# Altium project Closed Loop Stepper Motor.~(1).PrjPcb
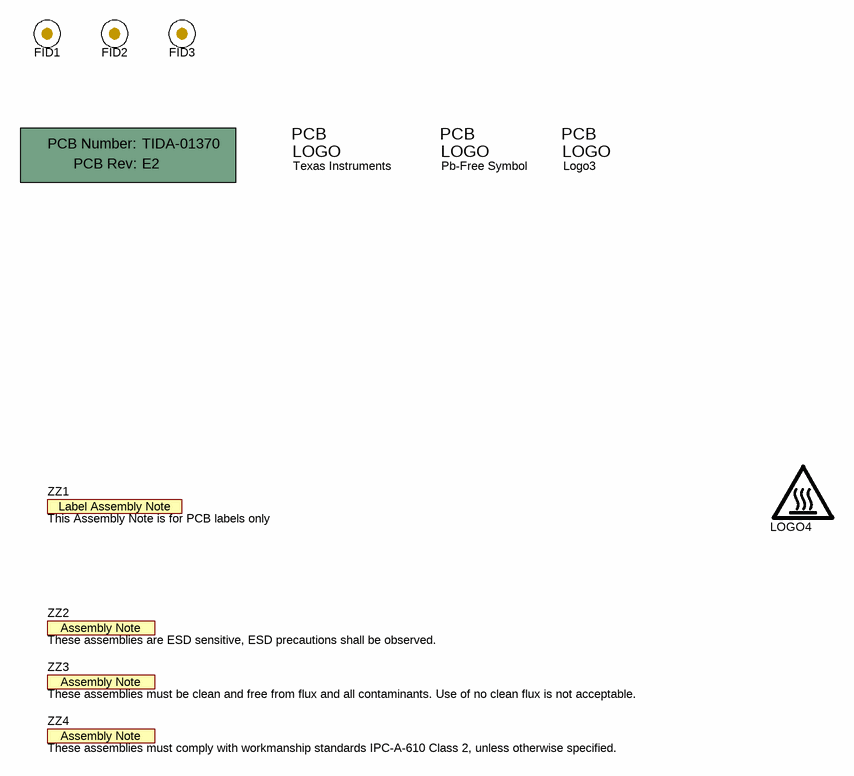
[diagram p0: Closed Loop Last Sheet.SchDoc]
TID: N/A; TechSupport: http://www.ti.com/support; SCH_Rev: E2; PRJ_Title: Change in menu Project|Project Options|Parameters; PRJ_Number: TIDA-01370; PRJ_Engineer: Rick Duncan; PRJ_Customer: Public Release; PCB_Rev: E2; PCB_Layout: Antonio Faggio; CopyrightYear: 2016
4 sheets, 67 parts. Net scope: global (net labels, ports and power ports of the same name join across sheets).
Board file: Closed Loop Stepper Motor Layout.PcbDoc
Sheets:
  Closed Loop Last Sheet.SchDoc
  Closed Loop PWR&Encoder.SchDoc
  Closed Loop DRV8880_MSP430.SchDoc
  Block Diagram_TIDA01370.SchDoc

## Sheet Closed Loop Last Sheet.SchDoc
size 431 x 279 mm; Date: Not shown in title block; ApprovedBy: Not shown in title block; CheckedBy: Not shown in title block; Author: Not shown in title block; CompanyName: Not shown in title block; Engineer: Not shown in title block; Organization: Not shown in title block; Address1: Not shown in title block; Address2: Not shown in title block; Address3: Not shown in title block; Address4: Not shown in title block; DocumentNumber: 4; Revision: Use project parameter SCH_Rev; SheetNumber: 4; SheetTotal: 4; PageSetup: Record=PageOptions¦CenterHorizontal=True¦CenterVertical=True¦PrintScale=1.00¦XCorrection=1.00¦YCorrection=1.00¦PrintKind=0¦BorderSize=5000000¦LeftOffset=0¦BottomOffset=0¦Orientation=2¦PaperLength=1000¦PaperWidth=1000¦Scale=100¦PaperSource=15¦PrintQuality=600¦MediaType=1¦DitherType=10¦PaperKind=Letter¦PrintScaleMode=1

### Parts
!PCB1  Printed Circuit Board  (value not drawn)  (mechanical)
FID1  Fiducial  [Fiducial10-20]  (value not drawn)
FID2  Fiducial  [Fiducial10-20]  (value not drawn)
FID3  Fiducial  [Fiducial10-20]  (value not drawn)
Logo1  Texas Instruments  [TI_Symbol_Overlay_Small]  (no BOM)
Logo2  Pb-Free Symbol  [Pb-Free_Overlay_Small]  (no BOM)
Logo3  FCC disclaimer  [FCC_disclaimer_stacked]  (value not drawn)  (no BOM)
LOGO4  CAUTION HOT SURFACE  [IEC_HotSurface_Small]  (value not drawn)  (no BOM)
ZZ1  This Assembly Note is for PCB labels only  [AssemblyNoteLabel]  (no BOM)
ZZ2  These assemblies are ESD sensitive, ESD precautions shall be observed.  [AssemblyNote]  (no BOM)
ZZ3  These assemblies must be clean and free from flux and all contaminants. Use of no clean flux is not acceptable.  [AssemblyNote]  (no BOM)
ZZ4  These assemblies must comply with workmanship standards IPC-A-610 Class 2, unless otherwise specified.  [AssemblyNote]  (no BOM)

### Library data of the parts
!PCB1 = PCB: Manufacturer: Any; PartNumber: TIDA-01370; SymbolCreator: a0412235
FID1-FID3 = Fiducial: Fiducial mark.  There is nothing to buy or mount.; SymbolCreator: codlsc
Logo1 = TI_Logo: Texas Instrument Corporate Signature; SymbolCreator: codlsc
Logo2 = Pb-Free: SymbolCreator: a0412235
Logo3 = FCC_disclaimer: SymbolCreator: a0412235
LOGO4 = IEC_HotSurface: IEC 61010-1 Hot Surface Warning; SymbolCreator: a0412235
ZZ1 = AssemblyNoteLabel: SymbolCreator: a0412235
ZZ2-ZZ4 = AssemblyNote: SymbolCreator: codlsc

## Sheet Closed Loop PWR&Encoder.SchDoc
size 431 x 279 mm; Date: Not shown in title block; ApprovedBy: Not shown in title block; CheckedBy: Not shown in title block; Author: Not shown in title block; CompanyName: Not shown in title block; Engineer: Not shown in title block; Organization: Not shown in title block; Address1: Not shown in title block; Address2: Not shown in title block; Address3: Not shown in title block; Address4: Not shown in title block; DocumentNumber: 3; Revision: Use project parameter SCH_Rev; SheetNumber: 3; SheetTotal: 4; PageSetup: Record=PageOptions¦CenterHorizontal=True¦CenterVertical=True¦PrintScale=1.00¦XCorrection=1.00¦YCorrection=1.00¦PrintKind=0¦BorderSize=5000000¦LeftOffset=0¦BottomOffset=0¦Orientation=2¦PaperLength=1000¦PaperWidth=1000¦Scale=100¦PaperSource=15¦PrintQuality=600¦MediaType=1¦DitherType=10¦PaperKind=Letter¦PrintScaleMode=1
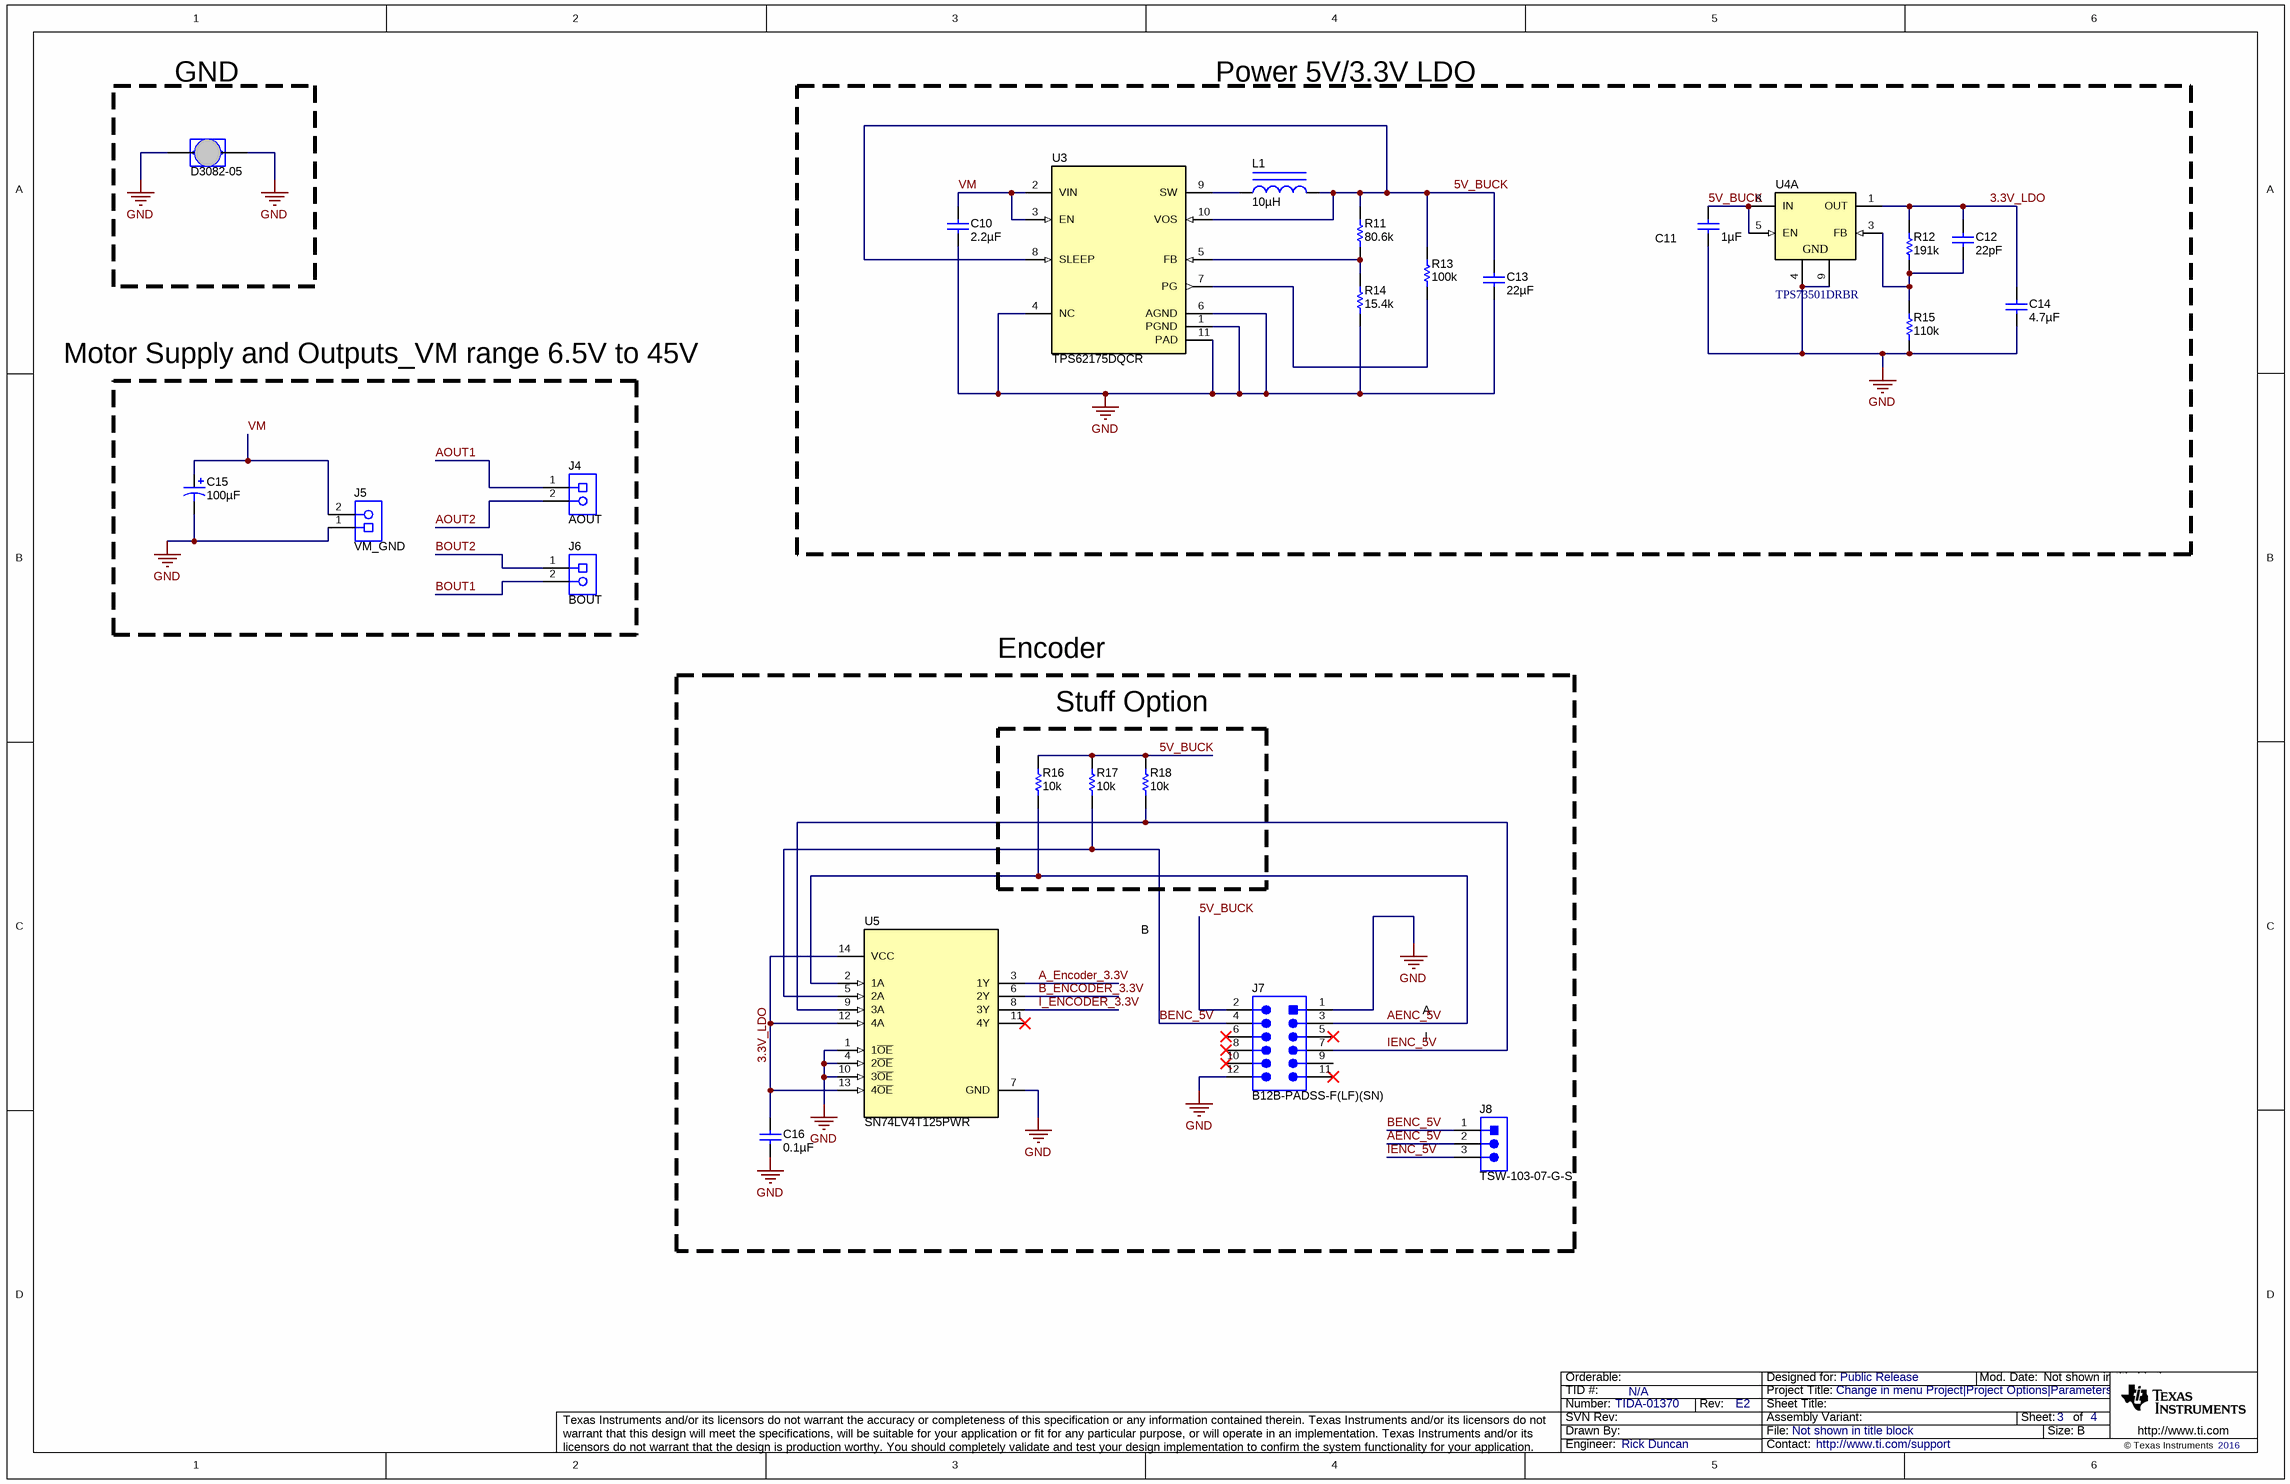
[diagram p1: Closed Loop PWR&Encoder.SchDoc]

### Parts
C10  ValueDisplayed: 2.2µF  [0805_HV]  (hidden comment: GRM21BR61E225KA12L)
C11  ValueDisplayed: 1µF  [0402L]  (hidden comment: C1005X5R0J105M050BB)
C12  ValueDisplayed: 22pF  [0402L]  (hidden comment: C1005C0G1H220J050BA)
C13  ValueDisplayed: 22µF  [1206_180]  (hidden comment: GRM31CR61A226ME19L)
C14  ValueDisplayed: 4.7µF  [0603L]  (hidden comment: GRM188R60J475KE19D)
C15  ValueDisplayed: 100µF  [SM_RADIAL_G]  (hidden comment: EEE-FK1J101P)
C16  ValueDisplayed: 0.1µF  [0603L]  (hidden comment: C0603C104K8RACTU)
J4  AOUT  [TERM_BLK_ED555-2DS]
J5  VM_GND  [TERM_BLK_ED555-2DS]
J6  BOUT  [TERM_BLK_ED555-2DS]
J7  B12B-PADSS-F(LF)(SN)  [JST_B12B-PADSS-F]
J8  TSW-103-07-G-S  [TSW-103-07-G-S]
L1  ValueDisplayed: 10µH  [WE-TPC_2828]  (hidden comment: 744025100)
R11  ValueDisplayed: 80.6k  [0402L]  (hidden comment: CRCW040280K6FKED)
R12  ValueDisplayed: 191k  [0402L]  (hidden comment: CRCW0402191KFKED)
R13  ValueDisplayed: 100k  [0402L]  (hidden comment: CRCW0402100KFKED)
R14  ValueDisplayed: 15.4k  [0402L]  (hidden comment: CRCW040215K4FKED)
R15  ValueDisplayed: 110k  [0402L]  (hidden comment: CRCW0402110KFKED)
R16  ValueDisplayed: 10k  [0603L]  (hidden comment: CRCW060310K0JNEA)
R17  ValueDisplayed: 10k  [0603L]  (hidden comment: CRCW060310K0JNEA)
R18  ValueDisplayed: 10k  [0603L]  (hidden comment: CRCW060310K0JNEA)
TP1  D3082-05  [Harwin_D3082-05]
U3  TPS62175DQCR  [DQC0010A]
U4  TPS73501DRBR  [DRB0008A]  (part A of 2)
U5  SN74LV4T125PWR  [PW0014A_N]

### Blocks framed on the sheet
GND: TP1
Power 5V/3.3V LDO: C10-C14 L1 R11-R15 U3 U4
Stuff Option: C16 J7 J8 R16-R18 U5

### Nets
3.3V_LDO: C12.1 C14.1 C16.1 R12.2 U4.1(OUT) U5.12(4A) U5.13(4~{OE}) U5.14(VCC)
GND: C10.2 C11.1 C13.2 C14.2 C15.2(-) C16.2 J5.1 J7.1 J7.12 R14.2 R15.1 TP1.1 TP1.2 U3.1(PGND) U3.4(NC) U3.6(AGND) U3.11(PAD) U4.4(GND) U4.9(GND) U5.1(1~{OE}) U5.4(2~{OE}) U5.7(GND) U5.10(3~{OE})
5V_BUCK: C11.2 C13.1 J7.2 L1.2 R11.2 R13.2 R16.2 R17.2 R18.2 U3.8(SLEEP) U3.10(VOS) U4.5(EN) U4.8(IN)
A_Encoder_3.3V: U5.3(1Y)
AENC_5V: J7.3 J8.2 R16.1 U5.2(1A)
AOUT1: J4.1
AOUT2: J4.2
B_ENCODER_3.3V: U5.6(2Y)
BENC_5V: J7.4 J8.1 R17.1 U5.5(2A)
BOUT1: J6.2
BOUT2: J6.1
I_ENCODER_3.3V: U5.8(3Y)
IENC_5V: J7.7 J8.3 R18.1 U5.9(3A)
VM: C10.1 C15.1(+) J5.2 U3.2(VIN) U3.3(EN)
NetC12_2: C12.2 R12.1 R15.2 U4.3(FB)
NetL1_1: L1.1 U3.9(SW)
NetR11_1: R11.1 R14.1 U3.5(FB)
NetR13_1: R13.1 U3.7(PG)

Not connected (* = marked no-connect by the designer): J7 5* 6* 8* 9 10* 11*; U5 11(4Y)*

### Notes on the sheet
- Motor Supply and Outputs_VM range 6.5V to 45V
- Encoder
- B
- A
- I

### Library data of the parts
C10 = GRM21BR61E225KA12L: CAP, CERM, 2.2 µF, 25 V, +/- 10%, X5R, 0805; Manufacturer: MuRata; Polarized: N; CompType: Capacitor; Value: 2.2uF; U/M: EA; Cap_F: 0.0000022; Tolerance_%: 10; ESR_ohm: 0.008; Value1: 0.008 ohm; VDC_V: 25; Value2: 25V; TaMin_C: -55; TaMax_C: 85; Cap_Case: 0805; SizeArea_mm2: 2.5; SizeAreaWB_mm2: 6.75; SizeX_mm: 2; SizeY_mm: 1.25; SizeZ_mm: 1.45; AEC Category: Q200
C11 = C1005X5R0J105M050BB: CAP, CERM, 1 µF, 6.3 V, +/- 20%, X5R, 0402; Manufacturer: TDK; Polarized: N; CompType: Capacitor; Value: 1uF; U/M: EA; Cap_F: 0.000001; Tolerance_%: 20; ESR_ohm: 0.0079; Value1: 0.0079 ohm; VDC_V: 6.3; Value2: 6.3V; TaMin_C: -55; TaMax_C: 85; Cap_Case: 0402; SizeArea_mm2: 0.5; SizeAreaWB_mm2: 3; SizeX_mm: 1; SizeZ_mm: 0.6; AEC Category: Q200
C12 = C1005C0G1H220J050BA: CAP, CERM, 22 pF, 50 V, +/- 5%, C0G/NP0, 0402; Manufacturer: TDK; Polarized: N; CompType: Capacitor; Value: 22pF; U/M: EA; Cap_F: 0.000000000022; Tolerance_%: 5; Value1: Unknown; VDC_V: 50; Value2: 50V; TaMin_C: -55; TaMax_C: 125; Cap_Case: 0402; SizeArea_mm2: 0.5; SizeAreaWB_mm2: 3; SizeX_mm: 1; SizeZ_mm: 0.6; AEC Category: Q200
C13 = GRM31CR61A226ME19L: CAP, CERM, 22 µF, 10 V, +/- 20%, X5R, 1206; Manufacturer: MuRata; Polarized: N; CompType: Capacitor; Value: 22uF; U/M: EA; Cap_F: 0.000022; Tolerance_%: 20; ESR_ohm: 0.007; Value1: 0.007 ohm; VDC_V: 10; Value2: 10V; TaMin_C: -55; TaMax_C: 85; Cap_Case: 1206; SizeArea_mm2: 5.12; SizeAreaWB_mm2: 10.92; SizeX_mm: 3.2; SizeY_mm: 1.6; SizeZ_mm: 1.8; AEC Category: Q200
C14 = GRM188R60J475KE19D: CAP, CERM, 4.7 µF, 6.3 V, +/- 10%, X5R, 0603; Manufacturer: MuRata; Polarized: N; CompType: Capacitor; Value: 4.7uF; U/M: EA; Cap_F: 0.0000047; Tolerance_%: 10; ESR_ohm: 0.005; Value1: 0.005 ohm; VDC_V: 6.3; Value2: 6.3V; IRMS_A: 2; TaMin_C: -55; TaMax_C: 85; Cap_Case: 0603; SizeArea_mm2: 1.28; SizeAreaWB_mm2: 4.68; SizeX_mm: 1.6; SizeY_mm: 0.8; SizeZ_mm: 1; AEC Category: Q200
C15 = EEE-FK1J101P: CAP, AL, 100 µF, 63 V, +/- 20%, 0.35 ohm, AEC-Q200 Grade 2, SMD; Manufacturer: Panasonic; Polarized: Y; CompType: Capacitor; Value: 100uF; U/M: EA; Cap_F: 0.0001; Tolerance_%: 20; VDC_V: 63; Value2: 63V; ESR_ohm: 0.35; IRMS_A: 0.4; TaMin_C: -55; TaMax_C: 105; Cap_Case: G; SizeAreaWB_mm2: 172.2; SizeArea_mm2: 123.6; SizeX_mm: 12; SizeY_mm: 10.3; SizeZ_mm: 10.2; AEC Category: Q200; AEC Grade: 2
C16 = C0603C104K8RACTU: CAP, CERM, 0.1 µF, 10 V, +/- 10%, X7R, 0603; Manufacturer: Kemet; Polarized: N; CompType: Capacitor; Value: 0.1uF; U/M: EA; Cap_F: 0.0000001; Tolerance_%: 10; Value1: Unknown; Value2: 10V; TaMin_C: -55; TaMax_C: 125; Cap_Case: 0603; SizeArea_mm2: 1.28; SizeAreaWB_mm2: 4.68; SizeX_mm: 1.6; SizeY_mm: 0.8; SizeZ_mm: 1; AEC Category: Q200
J4-J6 = ED555/2DS: Terminal Block, 3.5mm Pitch, 2x1, TH; Manufacturer: On-Shore Technology; SymbolCreator: a0412235; Pitch_mm: 3.5; Gender: Female; Shrouded: N; Row_Count: 1; ContactFinish: Brass; Current_A: 6; Voltage_V: 150; Cert_CULUS: Y
J7 = B12B-PADSS-F(LF)(SN): Header(Shrouded), 2mm, 6x2, Tin, TH; Manufacturer: JST Manufacturing; SymbolCreator: Altium; Pitch_mm: 2; Gender: Male; Shrouded: Y; Current_A: 3; Voltage_V: 250
J8 = TSW-103-07-G-S: Header, 100mil, 3x1, Gold, TH; Manufacturer: Samtec; SymbolCreator: a0799628; Pitch_mm: 2.54; Gender: Male; Shrouded: N; Row_Count: 1; Current_A: 6.3; Voltage_V: 550; Cert_CSA: Y
L1 = 744025100: Inductor, Shielded Drum Core, Ferrite, 10 µH, 1 A, 0.17 ohm, SMD; Manufacturer: Wurth Elektronik; Value: 10uH; Ind_H: 10.0E-6; Imax_A: 1; Irms: 1A @ 40C rise; Isat: 1.1A @ 35% inductance drop; DCR_ohm: 0.17; Value2: 1A; SizeAreaWB_mm2: 14.44; SizeArea_mm2: 7.84; SizeX_mm: 2.8; SizeZ_mm: 3; AEC Category: Q200
R11 = CRCW040280K6FKED: RES, 80.6 k, 1%, 0.063 W, 0402; Manufacturer: Vishay-Dale; CompType: Resistor; Value: 80.6k; Res_ohm: 80600; Value_Code: 80k6; Tolerance_%: 1; Power_W: 0.063; Value2: 0.063W; VDC_V: 50; TempCo: 100 ppm/C; SizeArea_mm2: 0.5; SizeZ_mm: 0.6; EIA_Code: E96; U/M: EA; AEC Category: Q200
R12 = CRCW0402191KFKED: RES, 191 k, 1%, 0.063 W, 0402; Manufacturer: Vishay-Dale; CompType: Resistor; Value: 191k; Res_ohm: 191000; Tolerance_%: 1; Power_W: 0.063; Value2: 0.063W; VDC_V: 50; TempCo: 100 ppm/C; SizeArea_mm2: 0.5; SizeZ_mm: 0.6; EIA_Code: E96; U/M: EA; AEC Category: Q200
R13 = CRCW0402100KFKED: RES, 100 k, 1%, 0.063 W, 0402; Manufacturer: Vishay-Dale; CompType: Resistor; Value: 100k; Res_ohm: 100000; Tolerance_%: 1; Power_W: 0.063; Value2: 0.063W; VDC_V: 50; TempCo: 100 ppm/C; SizeArea_mm2: 0.5; SizeZ_mm: 0.6; EIA_Code: E96; U/M: EA; AEC Category: Q200
R14 = CRCW040215K4FKED: RES, 15.4 k, 1%, 0.063 W, 0402; Manufacturer: Vishay-Dale; CompType: Resistor; Value: 15.4k; Res_ohm: 15400; Value_Code: 15k4; Tolerance_%: 1; Power_W: 0.063; Value2: 0.063W; VDC_V: 50; TempCo: 100 ppm/C; SizeArea_mm2: 0.5; SizeZ_mm: 0.6; EIA_Code: E96; U/M: EA; AEC Category: Q200
R15 = CRCW0402110KFKED: RES, 110 k, 1%, 0.063 W, 0402; Manufacturer: Vishay-Dale; CompType: Resistor; Value: 110k; Res_ohm: 110000; Tolerance_%: 1; Power_W: 0.063; Value2: 0.063W; VDC_V: 50; TempCo: 100 ppm/C; SizeArea_mm2: 0.5; SizeZ_mm: 0.6; EIA_Code: E96; U/M: EA; AEC Category: Q200
R16-R18 = CRCW060310K0JNEA: RES, 10 k, 5%, 0.1 W, 0603; Manufacturer: Vishay-Dale; CompType: Resistor; Value: 10k; Res_ohm: 10000; Value_Code: 10k0; Tolerance_%: 5; Power_W: 0.1; Value2: 0.1W; VDC_V: 75; TempCo: 200 ppm/C; SizeArea_mm2: 1.28; SizeX_mm: 1.6; SizeY_mm: 0.8; SizeZ_mm: 1; EIA_Code: E24; U/M: EA; AEC Category: Q200
TP1 = D3082-05: 1mm Uninsulated Shorting Plug, 10.16mm spacing, TH; Manufacturer: Harwin; SymbolCreator: a0799628; CompType: Jumper Wire
U3 = TPS62175DQCR: 28V, 0.5A Step-Down Converter with Sleep Mode, DQC0010A (WSON-10); Alternate PartNumber: TPS62175DQCT; Manufacturer: Texas Instruments; SymbolCreator: a0411947; SizeArea_mm2: 6; SizeAreaWB_mm2: 12; SizeX_mm: 2; SizeY_mm: 3; SizeZ_mm: 0.8; CompType: IC; U/M: EA
U4 = TPS73501DRBR: Single Output High PSRR LDO, 500 mA, Adjustable 1.25 to 6 V Output, 2.7 to 6.5 V Input, with Low IQ, 8-pin SON (DRB), -40 to 125 degC, Green (RoHS & no Sb/Br); Manufacturer: Texas Instruments; Alternate PartNumber: Equivalent; Accuracy(%): 2; Iout(Max)(A): 0.5; Iq(Typ)(mA): 0.04; SubFamily: Single Channel LDO; Vdo(Typ)(mV): 280; Vin(Max)(V): 6.5; Vin(Min)(V): 2.7; Vout Adj(Max)(V): 6; Vout Adj(Min)(V): 1.25
U5 = SN74LV4T125PWR: Single Power Supply Quadruple Buffer Translator GATE With 3-State Output CMOS Logic Level Shifter, PW0014A (TSSOP-14); Manufacturer: Texas Instruments; SymbolCreator: Altium; SizeArea_mm2: 32; SizeAreaWB_mm2: 58.8; SizeX_mm: 6.4; SizeY_mm: 5; SizeZ_mm: 1.2; CompType: IC; U/M: EA

## Sheet Closed Loop DRV8880_MSP430.SchDoc
size 431 x 279 mm; Date: Not shown in title block; ApprovedBy: Not shown in title block; CheckedBy: Not shown in title block; Author: Not shown in title block; CompanyName: Not shown in title block; Engineer: Not shown in title block; Organization: Not shown in title block; Address1: Not shown in title block; Address2: Not shown in title block; Address3: Not shown in title block; Address4: Not shown in title block; DocumentNumber: 2; Revision: Use project parameter SCH_Rev; SheetNumber: 2; SheetTotal: 4; PageSetup: Record=PageOptions¦CenterHorizontal=True¦CenterVertical=True¦PrintScale=0.62¦XCorrection=1.00¦YCorrection=1.00¦PrintKind=0¦BorderSize=5000000¦LeftOffset=0¦BottomOffset=0¦Orientation=2¦PaperLength=1000¦PaperWidth=1000¦Scale=100¦PaperSource=15¦PrintQuality=600¦MediaType=1¦DitherType=10¦PrintScaleMode=1¦PaperKind=Letter
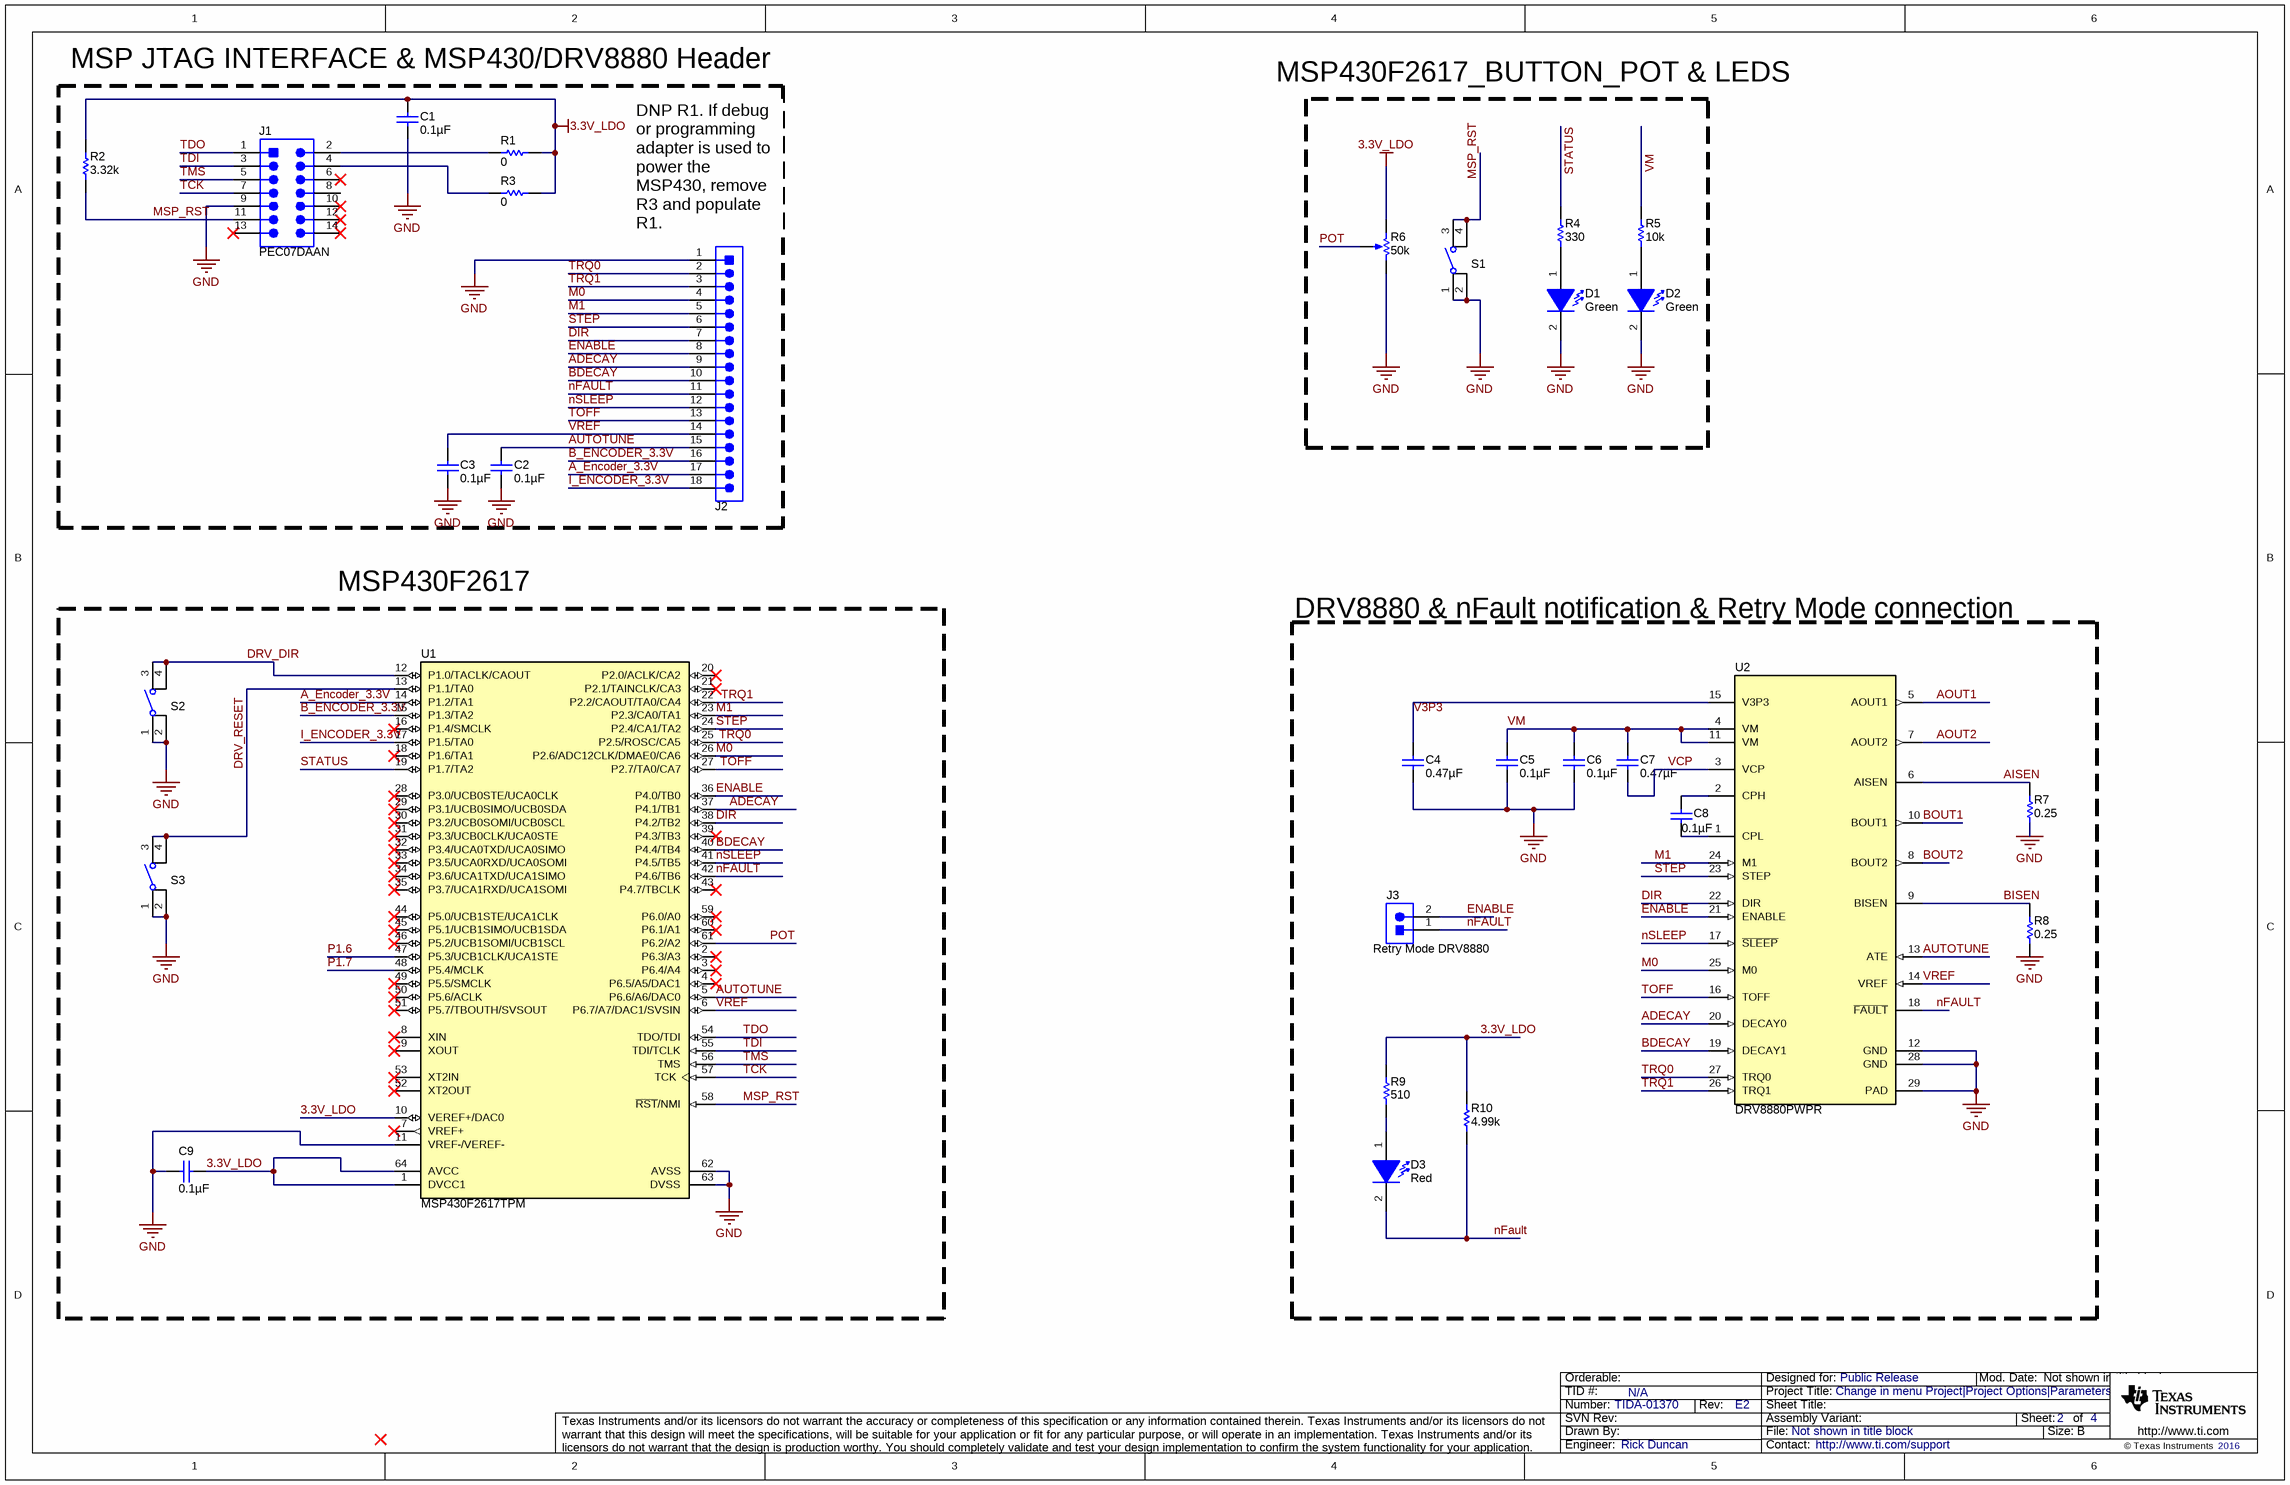
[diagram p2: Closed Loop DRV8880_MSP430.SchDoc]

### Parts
C1  ValueDisplayed: 0.1µF  [0402L]  (hidden comment: GRM155R61A104KA01D)
C2  ValueDisplayed: 0.1µF  [0402L]  (hidden comment: GRM155R61A104KA01D)
C3  ValueDisplayed: 0.1µF  [0402L]  (hidden comment: GRM155R61A104KA01D)
C4  ValueDisplayed: 0.47µF  [0603L]  (hidden comment: C0603C474K9RACTU)
C5  ValueDisplayed: 0.1µF  [0805L]  (hidden comment: C0805C104K1RACTU)
C6  ValueDisplayed: 0.1µF  [0805L]  (hidden comment: C0805C104K1RACTU)
C7  ValueDisplayed: 0.47µF  [0805L]  (hidden comment: 0805YC474KAT2A)
C8  ValueDisplayed: 0.1µF  [0805L]  (hidden comment: GRM21BR71E104KA01L)
C9  ValueDisplayed: 0.1µF  [0402L]  (hidden comment: GRM155R61A104KA01D)
D1  value Green  [LED_LTST-C171]  (hidden comment: LTST-C171GKT)
D2  value Green  [LED_LTST-C171]  (hidden comment: LTST-C171GKT)
D3  value Red  [LED_LTST-C190_Red]  (hidden comment: LTST-C190CKT)
J1  PEC07DAAN  [CONN_PEC07DAAN]
J2  TSW-118-07-G-S  [TSW-118-07-G-S]  (value not drawn)
J3  Retry Mode DRV8880  [CONN_90120-0122]
R1  ValueDisplayed: 0  [0402L]  (hidden comment: ERJ-2GE0R00X)
R2  ValueDisplayed: 3.32k  [0402L]  (hidden comment: CRCW04023K32FKED)
R3  ValueDisplayed: 0  [0402L]  (hidden comment: ERJ-2GE0R00X)
R4  ValueDisplayed: 330  [0603L]  (hidden comment: CRCW0603330RJNEA)
R5  ValueDisplayed: 10k  [0603L]  (hidden comment: CRCW060310K0JNEA)
R6  value 50k  [Bourns_3352T]  (hidden comment: 3352T-1-503LF)
R7  ValueDisplayed: 0.25  [2010L]  (hidden comment: CSRN2010FKR250)
R8  ValueDisplayed: 0.25  [2010L]  (hidden comment: CSRN2010FKR250)
R9  ValueDisplayed: 510  [0402L]  (hidden comment: CRCW0402510RJNED)
R10  ValueDisplayed: 4.99k  [0402L]  (hidden comment: CRCW04024K99FKED)
S1  4-1437565-1  [SW_FSM4JSMA]  (value not drawn)
S2  4-1437565-1  [SW_FSM4JSMA]  (value not drawn)
S3  4-1437565-1  [SW_FSM4JSMA]  (value not drawn)
U1  MSP430F2617TPM  [PM0064A_N]
U2  DRV8880PWPR  [PWP0028C_N]

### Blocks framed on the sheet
DRV8880 & nFault notification & Retry Mode connection: C4-C8 D3 J3 R7-R10 U2

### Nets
3.3V_LDO: C1.1 C9.2 R1.2 R2.2 R3.2 R6.3(CW) R9.2 R10.2 U1.1(DVCC1) U1.10(VEREF+/DAC0) U1.64(AVCC)
GND: C1.2 C2.2 C3.2 C4.2 C5.2 C6.2 C9.1 D1.2(K) D2.2(K) J1.9 J2.1 R6.1(CCW) R7.1 R8.1 S1.1 S1.2 S2.1 S2.2 S3.1 S3.2 U1.11(VREF-/VEREF-) U1.62(AVSS) U1.63(DVSS) U2.12(GND) U2.28(GND) U2.29(PAD)
A_Encoder_3.3V: J2.17 U1.14(P1.2/TA1)
ADECAY: J2.9 U1.37(P4.1/TB1) U2.20(DECAY0)
AISEN: R7.2 U2.6(AISEN)
AOUT1: U2.5(AOUT1)
AOUT2: U2.7(AOUT2)
AUTOTUNE: C2.1 J2.15 U1.5(P6.6/A6/DAC0) U2.13(ATE)
B_ENCODER_3.3V: J2.16 U1.15(P1.3/TA2)
BDECAY: J2.10 U1.40(P4.4/TB4) U2.19(DECAY1)
BISEN: R8.2 U2.9(BISEN)
BOUT1: U2.10(BOUT1)
BOUT2: U2.8(BOUT2)
DIR: J2.7 U1.38(P4.2/TB2) U2.22(DIR)
DRV_DIR: S2.3 S2.4 U1.12(P1.0/TACLK/CAOUT)
DRV_RESET: S3.3 S3.4 U1.13(P1.1/TA0)
ENABLE: J2.8 J3.2 U1.36(P4.0/TB0) U2.21(ENABLE)
I_ENCODER_3.3V: J2.18 U1.17(P1.5/TA0)
M0: J2.4 U1.26(P2.6/ADC12CLK/DMAE0/CA6) U2.25(M0)
M1: J2.5 U1.23(P2.3/CA0/TA1) U2.24(M1)
MSP_RST: J1.11 R2.1 S1.3 S1.4 U1.58(~{RST}/NMI)
nFAULT: D3.2(K) J2.11 J3.1 R10.1 U1.42(P4.6/TB6) U2.18(~{FAULT})
nSLEEP: J2.12 U1.41(P4.5/TB5) U2.17(~{SLEEP})
P1.6: U1.47(P5.3/UCB1CLK/UCA1STE)
P1.7: U1.48(P5.4/MCLK)
POT: R6.2(WIPER) U1.61(P6.2/A2)
STATUS: R4.2 U1.19(P1.7/TA2)
STEP: J2.6 U1.24(P2.4/CA1/TA2) U2.23(STEP)
TCK: J1.7 U1.57(TCK)
TDI: J1.3 U1.55(TDI/TCLK)
TDO: J1.1 U1.54(TDO/TDI)
TMS: J1.5 U1.56(TMS)
TOFF: J2.13 U1.27(P2.7/TA0/CA7) U2.16(TOFF)
TRQ0: J2.2 U1.25(P2.5/ROSC/CA5) U2.27(TRQ0)
TRQ1: J2.3 U1.22(P2.2/CAOUT/TA0/CA4) U2.26(TRQ1)
V3P3: C4.1 U2.15(V3P3)
VCP: C7.1 U2.3(VCP)
VM: C5.1 C6.1 C7.2 R5.2 U2.4(VM) U2.11(VM)
VREF: C3.1 J2.14 U1.6(P6.7/A7/DAC1/SVSIN) U2.14(VREF)
NetC8_1: C8.1 U2.2(CPH)
NetC8_2: C8.2 U2.1(CPL)
NetD1_1: D1.1(A) R4.1
NetD2_1: D2.1(A) R5.1
NetD3_1: D3.1(A) R9.1
NetJ1_2: J1.2 R1.1
NetJ1_4: J1.4 R3.1

Not connected (* = marked no-connect by the designer): J1 6* 8 10* 12* 13* 14*; U1 2(P6.3/A3)* 3(P6.4/A4)* 4(P6.5/A5/DAC1)* 7(VREF+)* 8(XIN)* 9(XOUT)* 16(P1.4/SMCLK)* 18(P1.6/TA1)* 20(P2.0/ACLK/CA2)* 21(P2.1/TAINCLK/CA3)* 28(P3.0/UCB0STE/UCA0CLK)* 29(P3.1/UCB0SIMO/UCB0SDA)* 30(P3.2/UCB0SOMI/UCB0SCL)* 31(P3.3/UCB0CLK/UCA0STE)* 32(P3.4/UCA0TXD/UCA0SIMO)* 33(P3.5/UCA0RXD/UCA0SOMI)* 34(P3.6/UCA1TXD/UCA1SIMO)* 35(P3.7/UCA1RXD/UCA1SOMI)* 39(P4.3/TB3)* 43(P4.7/TBCLK)* 44(P5.0/UCB1STE/UCA1CLK)* 45(P5.1/UCB1SIMO/UCB1SDA)* 46(P5.2/UCB1SOMI/UCB1SCL)* 49(P5.5/SMCLK)* 50(P5.6/ACLK)* 51(P5.7/TBOUTH/SVSOUT)* 52(XT2OUT)* 53(XT2IN)* 59(P6.0/A0)* 60(P6.1/A1)*

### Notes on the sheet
- (near C1) MSP JTAG INTERFACE & MSP430/DRV8880 Header
- MSP430F2617_BUTTON_POT & LEDS
- (near J2) DNP R1. If debug or programming adapter is used to power the MSP430, remove R3 and populate R1.
- MSP430F2617

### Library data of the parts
C1-C3 C9 = GRM155R61A104KA01D: CAP, CERM, 0.1 µF, 10 V, +/- 10%, X5R, 0402; Manufacturer: MuRata; Polarized: N; CompType: Capacitor; Value: 0.1uF; U/M: EA; Cap_F: 0.0000001; Tolerance_%: 10; Value1: Unknown; Value2: 10V; TaMin_C: -55; TaMax_C: 85; Cap_Case: 0402; SizeArea_mm2: 0.5; SizeAreaWB_mm2: 3; SizeX_mm: 1; SizeZ_mm: 0.6; AEC Category: Q200
C4 = C0603C474K9RACTU: CAP, CERM, 0.47 µF, 6.3 V, +/- 10%, X7R, 0603; Manufacturer: Kemet; Polarized: N; CompType: Capacitor; Value: 0.47uF; U/M: EA; Cap_F: 0.00000047; Tolerance_%: 10; Value1: Unknown; VDC_V: 6.3; Value2: 6.3V; TaMin_C: -55; TaMax_C: 125; Cap_Case: 0603; SizeArea_mm2: 1.28; SizeAreaWB_mm2: 4.68; SizeX_mm: 1.6; SizeY_mm: 0.8; SizeZ_mm: 1; AEC Category: Q200
C5 C6 = C0805C104K1RACTU: CAP, CERM, 0.1 µF, 100 V, +/- 10%, X7R, 0805; Manufacturer: Kemet; Polarized: N; CompType: Capacitor; Value: 0.1uF; U/M: EA; Cap_F: 0.0000001; Tolerance_%: 10; ESR_ohm: 0.064; Value1: 0.064 ohm; VDC_V: 100; Value2: 100V; IRMS_A: 1.64; TaMin_C: -55; TaMax_C: 125; Cap_Case: 0805; SizeArea_mm2: 2.5; SizeAreaWB_mm2: 6.75; SizeX_mm: 2; SizeY_mm: 1.25; SizeZ_mm: 1.45; AEC Category: Q200
C7 = 0805YC474KAT2A: CAP, CERM, 0.47 µF, 16 V, +/- 10%, X7R, 0805; Manufacturer: AVX; Polarized: N; CompType: Capacitor; Value: 0.47uF; U/M: EA; Cap_F: 0.00000047; Tolerance_%: 10; ESR_ohm: 0.011; Value1: 0.011 ohm; VDC_V: 16; Value2: 16V; TaMin_C: -55; TaMax_C: 125; Cap_Case: 0805; SizeArea_mm2: 2.5; SizeAreaWB_mm2: 6.75; SizeX_mm: 2; SizeY_mm: 1.25; SizeZ_mm: 1.45; AEC Category: Q200
C8 = GRM21BR71E104KA01L: CAP, CERM, 0.1 µF, 25 V, +/- 10%, X7R, 0805; Manufacturer: MuRata; Polarized: N; CompType: Capacitor; Value: 0.1uF; U/M: EA; Cap_F: 0.0000001; Tolerance_%: 10; Value1: Unknown; VDC_V: 25; Value2: 25V; TaMin_C: -55; TaMax_C: 125; Cap_Case: 0805; SizeArea_mm2: 2.5; SizeAreaWB_mm2: 6.75; SizeX_mm: 2; SizeY_mm: 1.25; SizeZ_mm: 1.45; AEC Category: Q200
D1 D2 = LTST-C171GKT: LED, Green, SMD; Manufacturer: Lite-On; Type: AlInGaP; Vf_V: 2.1; Value2: 2.1V; Io_A: 20; Value1: W; SizeAreaWB_mm2: 6.75; SizeArea_mm2: 2.5; SizeX_mm: 2; SizeY_mm: 1.25; SizeZ_mm: 1.2; U/M: EA
D3 = LTST-C190CKT: LED, Red, SMD; Manufacturer: Lite-On; Vf_V: 2; Value2: 2V; Io_A: 0.02; Tjmax_C: 85; Power_TotalModule: 0.0625; Value1: 0.0625W; U/M: EA
J1 = PEC07DAAN: Header, 100mil, 7x2, Tin, TH; Manufacturer: Sullins Connector Solutions; SymbolCreator: a0412235; Pitch_mm: 2.54; Gender: Male; Shrouded: N; Row_Count: 2; Current_A: 3; Voltage_V: 1800; Cert_UL: Y
J2 = TSW-118-07-G-S: Header, 100mil, 18x1, Gold, TH; Manufacturer: Samtec; SymbolCreator: a0411947; Pitch_mm: 2.54; Gender: Male; Shrouded: N; Row_Count: 1; Current_A: 6.3; Voltage_V: 550; Cert_CSA: Y
J3 = 90120-0122: Header, 100mil, 2x1, Tin, TH; Manufacturer: Molex; SymbolCreator: a0412235
R1 R3 = ERJ-2GE0R00X: RES, 0, 5%, 0.063 W, 0402; Manufacturer: Panasonic; CompType: Resistor; Value: 0; Value_Code: 0000; Tolerance_%: 5; Power_W: 0.063; Value2: 0.063W; VDC_V: 50; TempCo: 600 ppm/C; SizeArea_mm2: 0.5; SizeX_mm: 1; SizeZ_mm: 0.6; EIA_Code: E24; U/M: EA; AEC Category: Q200
R2 = CRCW04023K32FKED: RES, 3.32 k, 1%, 0.063 W, 0402; Manufacturer: Vishay-Dale; CompType: Resistor; Value: 3.32k; Res_ohm: 3320; Value_Code: 3k32; Tolerance_%: 1; Power_W: 0.063; Value2: 0.063W; VDC_V: 50; TempCo: 100 ppm/C; SizeArea_mm2: 0.5; SizeZ_mm: 0.6; EIA_Code: E96; U/M: EA; AEC Category: Q200
R4 = CRCW0603330RJNEA: RES, 330, 5%, 0.1 W, 0603; Manufacturer: Vishay-Dale; CompType: Resistor; Value: 330; Value_Code: 330R; Tolerance_%: 5; Power_W: 0.1; Value2: 0.1W; VDC_V: 75; TempCo: 200 ppm/C; SizeArea_mm2: 1.28; SizeX_mm: 1.6; SizeY_mm: 0.8; SizeZ_mm: 1; EIA_Code: E24; U/M: EA; AEC Category: Q200
R5 = CRCW060310K0JNEA: as R16 on sheet Closed Loop PWR&Encoder
R6 = 3352T-1-503LF: Trimming Potentiometer, 50K, 0.5W, TH; Manufacturer: Bourns; Sim Note: Enter the Resistance value and the set point into parameter fields.; SymbolCreator: a0412235; CompType: Trimmer
R7 R8 = CSRN2010FKR250: RES, 0.25, 1%, 1 W, 2010; Manufacturer: Stackpole Electronics Inc; CompType: Resistor; Value: 0.25; Value_Code: R250; Tolerance_%: 1; Value2: 1W; TempCo: 250 ppm/C; SizeArea_mm2: 12.5; SizeX_mm: 5; SizeY_mm: 2.5; SizeZ_mm: 1.66; U/M: EA; AEC Category: Q200
R9 = CRCW0402510RJNED: RES, 510, 5%, 0.063 W, 0402; Manufacturer: Vishay-Dale; CompType: Resistor; Value: 510; Value_Code: 510R; Tolerance_%: 5; Power_W: 0.063; Value2: 0.063W; VDC_V: 50; TempCo: 200 ppm/C; SizeArea_mm2: 0.5; SizeX_mm: 1; SizeZ_mm: 0.6; EIA_Code: E24; U/M: EA; AEC Category: Q200
R10 = CRCW04024K99FKED: RES, 4.99 k, 1%, 0.063 W, 0402; Manufacturer: Vishay-Dale; CompType: Resistor; Value: 4.99k; Res_ohm: 4990; Value_Code: 4k99; Tolerance_%: 1; Power_W: 0.063; Value2: 0.063W; VDC_V: 50; TempCo: 100 ppm/C; SizeArea_mm2: 0.5; SizeZ_mm: 0.6; EIA_Code: E96; U/M: EA; AEC Category: Q200
S1-S3 = 4-1437565-1: Switch, Tactile, SPST-NO, 0.05A, 12V, SMT; Manufacturer: TE Connectivity; SymbolCreator: a0412235; VDC_V: 12; SwitchFunction: Off-Mom; PositionCount: 1; CurrentRating_mA: 50
U1 = MSP430F2617TPM: 16 MHz Mixed Signal Microcontroller with 92 KB Flash, 8192 B SRAM and 48 GPIOs, -40 to 105 degC, 64-pin QFP (PM), Green (RoHS & no Sb/Br); Alternate Manufacturer: Texas Instruments; Alternate PartNumber: Equivalent; ADC: 12-bit SAR; ADC Channels: 8; Brown Out Reset: Yes; DMA: 3; Flash(KB): 92; Frequency(MHz): 16; GPIO: 48; Multiplier: 16x16; Pin/Package: 64LQFP; SRAM(B): 8192; SubFamily: 2 Series, Extended Temp; Timers - 16-bit: 2
U2 = DRV8880PWPR: 2-A 45-V 1/16-μstep Stepper Motor Driver With AutoTune, PWP0028C (TSSOP-28); Manufacturer: Texas Instruments; SymbolCreator: Altium; SizeArea_mm2: 62.08; SizeAreaWB_mm2: 98.28; SizeX_mm: 6.4; SizeY_mm: 9.7; SizeZ_mm: 1.2; CompType: IC; U/M: EA

## Sheet Block Diagram_TIDA01370.SchDoc
size 431 x 279 mm; Date: Not shown in title block; ApprovedBy: Not shown in title block; CheckedBy: Not shown in title block; Author: Not shown in title block; CompanyName: Not shown in title block; Engineer: Not shown in title block; Organization: Not shown in title block; Address1: Not shown in title block; Address2: Not shown in title block; Address3: Not shown in title block; Address4: Not shown in title block; DocumentNumber: 1; Revision: Use project parameter SCH_Rev; SheetNumber: 1; SheetTotal: 4; PageSetup: Record=PageOptions¦CenterHorizontal=True¦CenterVertical=True¦PrintScale=1.00¦XCorrection=1.00¦YCorrection=1.00¦PrintKind=0¦BorderSize=5000000¦LeftOffset=0¦BottomOffset=0¦Orientation=2¦PaperLength=1000¦PaperWidth=1000¦Scale=100¦PaperSource=15¦PrintQuality=600¦MediaType=1¦DitherType=10¦PaperKind=Letter¦PrintScaleMode=1
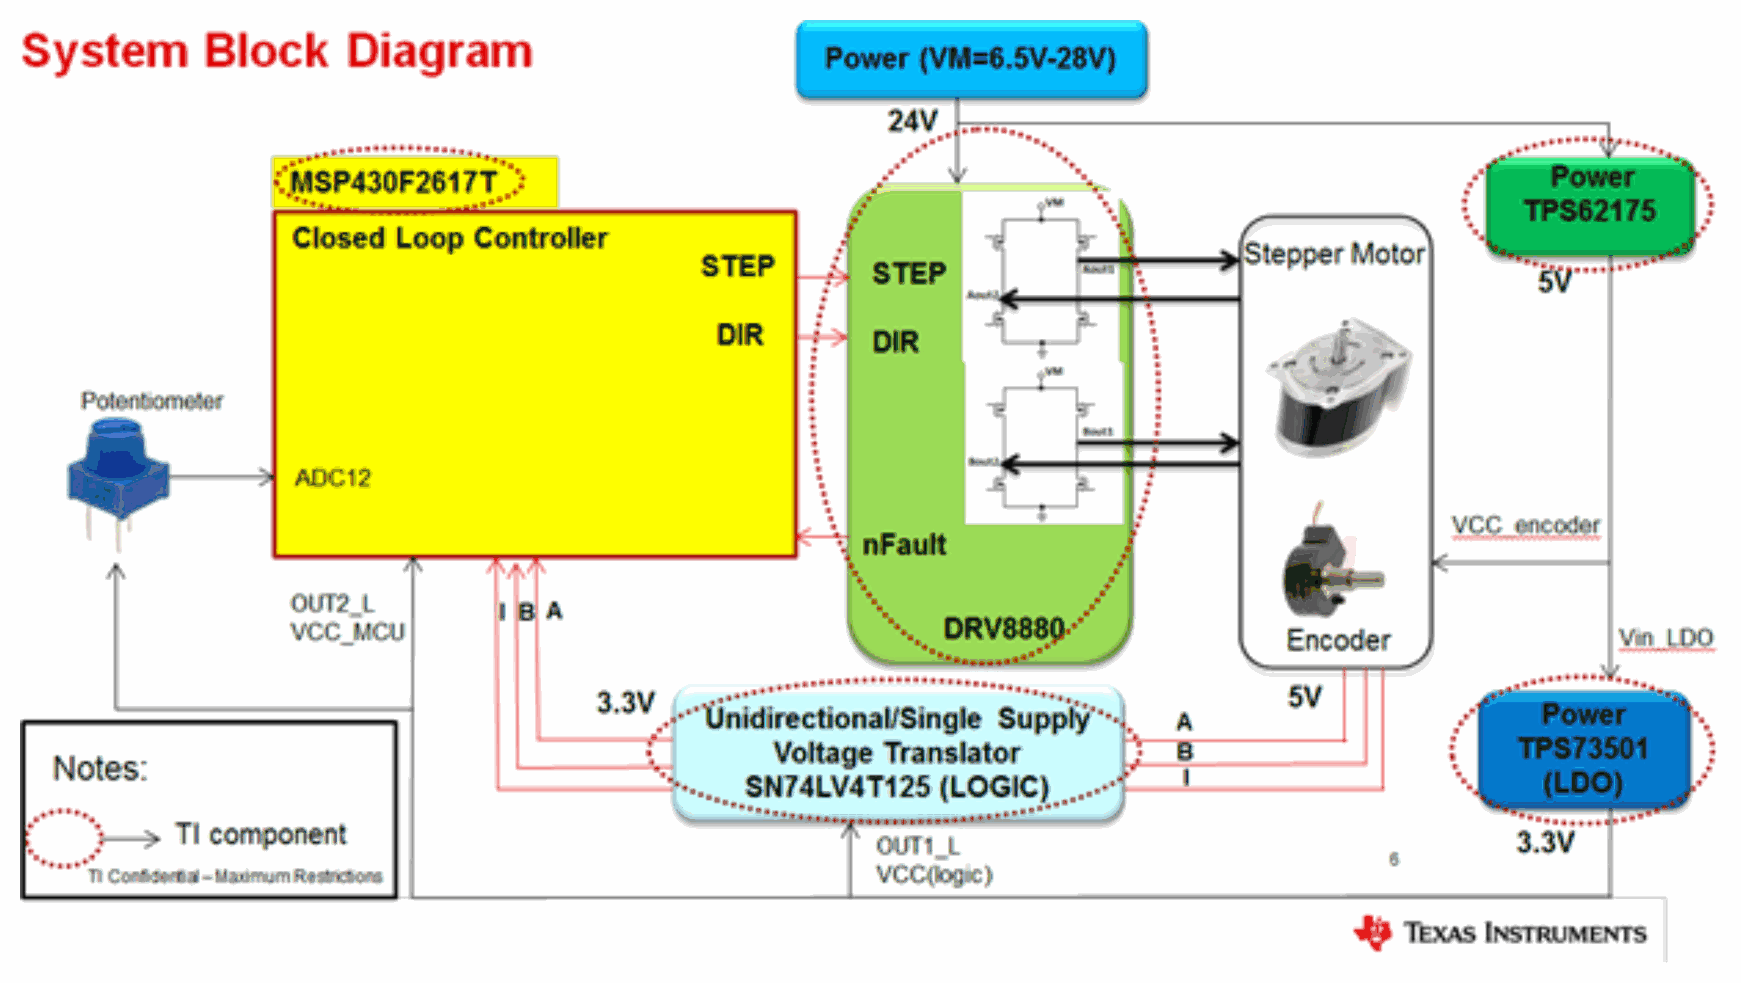
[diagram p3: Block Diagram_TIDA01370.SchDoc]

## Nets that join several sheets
3.3V_LDO: Closed Loop PWR&Encoder (8 pins), Closed Loop DRV8880_MSP430 (11 pins)
GND: Closed Loop PWR&Encoder (23 pins), Closed Loop DRV8880_MSP430 (26 pins)
A_Encoder_3.3V: Closed Loop PWR&Encoder (U5.3), Closed Loop DRV8880_MSP430 (J2.17 U1.14)
AOUT1: Closed Loop PWR&Encoder (J4.1), Closed Loop DRV8880_MSP430 (U2.5)
AOUT2: Closed Loop PWR&Encoder (J4.2), Closed Loop DRV8880_MSP430 (U2.7)
B_ENCODER_3.3V: Closed Loop PWR&Encoder (U5.6), Closed Loop DRV8880_MSP430 (J2.16 U1.15)
BOUT1: Closed Loop PWR&Encoder (J6.2), Closed Loop DRV8880_MSP430 (U2.10)
BOUT2: Closed Loop PWR&Encoder (J6.1), Closed Loop DRV8880_MSP430 (U2.8)
I_ENCODER_3.3V: Closed Loop PWR&Encoder (U5.8), Closed Loop DRV8880_MSP430 (J2.18 U1.17)
VM: Closed Loop PWR&Encoder (5 pins), Closed Loop DRV8880_MSP430 (6 pins)

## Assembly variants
001: not fitted J2 J8 R1 R16 R17 R18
